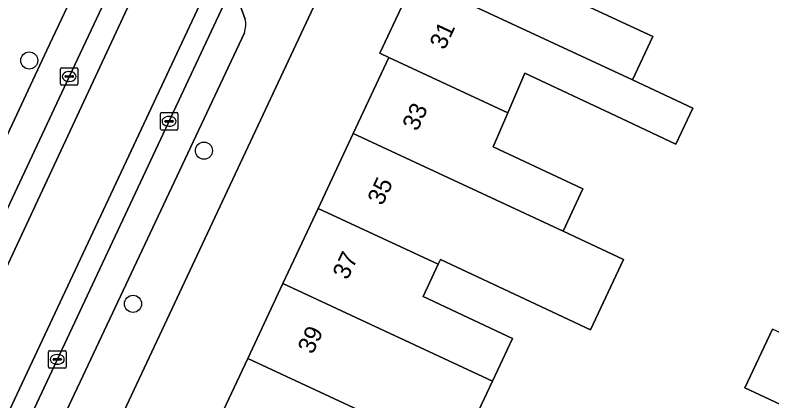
# Model space of a CAD drawing. Extents: x 159817 to 160765, y 380688 to 381638.
# Drawn here: x 160172.67 to 160215.98, y 381447.69 to 381469.78 of the extents above; entities that cross this region are included whole.
import ezdxf

# ---------------------------------------------------------------- set-up
doc = ezdxf.new("R2010")
doc.units = 0
for name, color, linetype in [('IMGEO_Boom', 7, 'Continuous'), ('IMGEO_Erf', 7, 'Continuous'), ('IMGEO_Kolk', 7, 'Continuous'), ('IMGEO_Pand', 7, 'Continuous'), ('IMGEO_Pand_nummerreeks', 7, 'Continuous'), ('IMGEO_Parkeervlak_open', 7, 'Continuous'), ('IMGEO_Rijbaan_lokaal_gesloten', 7, 'Continuous'), ('IMGEO_Voetpad_open', 7, 'Continuous')]:
    doc.layers.add(name, color=color, linetype=linetype)

msp = doc.modelspace()

# ---------------------------------------------------------------- linework, layer by layer
at = {"layer": 'IMGEO_Boom'}
for centre in [(160173.484, 381467.183), (160183.481, 381462.021), (160179.421, 381453.251)]:
    msp.add_circle(centre, 0.489, dxfattribs=at)
at = {"layer": 'IMGEO_Erf'}
for points in [[(160172.106, 381420.527), (160173.906, 381424.363), (160175.92, 381428.657), (160177.933, 381432.951), (160179.947, 381437.246), (160181.961, 381441.54), (160183.974, 381445.834), (160185.989, 381450.129), (160188.002, 381454.423), (160190.016, 381458.718), (160192.029, 381463.01), (160194.069, 381467.36), (160193.546, 381467.606), (160195.55, 381471.879), (160197.584, 381476.216), (160197.129, 381476.429), (160199.262, 381480.978), (160201.503, 381485.755), (160199.508, 381486.738), (160197.851, 381487.555), (160159.202, 381405.137)], [(160203.985, 381470.986), (160209.172, 381468.554), (160208.007, 381466.071), (160211.452, 381464.455), (160210.489, 381462.401), (160207.044, 381464.017), (160201.848, 381466.454), (160200.865, 381464.184), (160200.025, 381462.242), (160205.171, 381459.829), (160204.036, 381457.408), (160207.487, 381455.79), (160205.6, 381451.766), (160202.149, 381453.384), (160197.009, 381455.781), (160196.884, 381455.515), (160196.019, 381453.67), (160201.137, 381451.27), (160199.993, 381448.832), (160199.021, 381446.759)], [(160217.334, 381447.084), (160214.435, 381448.436), (160216.017, 381451.806)]]:
    msp.add_lwpolyline(points, dxfattribs=at)
at = {"layer": 'IMGEO_Kolk'}
for p, q in [((160175.267, 381465.842), (160175.267, 381466.694)), ((160175.342, 381466.768), (160176.194, 381466.768)), ((160176.268, 381466.694), (160176.268, 381465.842)), ((160175.526, 381466.262), (160175.526, 381466.274)), ((160175.964, 381466.225), (160175.566, 381466.225)), ((160175.569, 381466.311), (160175.967, 381466.311)), ((160175.755, 381466.548), (160175.78, 381466.548)), ((160176.01, 381466.274), (160176.01, 381466.262)), ((160176.194, 381465.768), (160175.342, 381465.768)), ((160175.778, 381465.988), (160175.753, 381465.988)), ((160180.985, 381463.278), (160180.985, 381464.13)), ((160181.06, 381464.204), (160181.912, 381464.204)), ((160181.986, 381464.13), (160181.986, 381463.278)), ((160181.244, 381463.698), (160181.244, 381463.71)), ((160181.682, 381463.661), (160181.284, 381463.661)), ((160181.287, 381463.747), (160181.685, 381463.747)), ((160181.473, 381463.984), (160181.498, 381463.984)), ((160181.728, 381463.71), (160181.728, 381463.698)), ((160181.912, 381463.204), (160181.06, 381463.204)), ((160181.496, 381463.424), (160181.471, 381463.424)), ((160174.588, 381449.643), (160174.588, 381450.495)), ((160174.663, 381450.569), (160175.515, 381450.569)), ((160175.076, 381450.349), (160175.101, 381450.349)), ((160175.589, 381450.495), (160175.589, 381449.643)), ((160174.847, 381450.063), (160174.847, 381450.075)), ((160175.285, 381450.026), (160174.887, 381450.026)), ((160174.89, 381450.112), (160175.288, 381450.112)), ((160175.099, 381449.789), (160175.074, 381449.789)), ((160175.331, 381450.075), (160175.331, 381450.063)), ((160175.515, 381449.569), (160174.663, 381449.569))]:
    msp.add_line(p, q, dxfattribs=at)
for points in [[(160175.267, 381465.842), (160175.267, 381466.694)], [(160175.342, 381466.768), (160176.194, 381466.768)], [(160176.268, 381466.694), (160176.268, 381465.842)], [(160176.194, 381465.768), (160175.342, 381465.768)], [(160180.985, 381463.278), (160180.985, 381464.13)], [(160181.06, 381464.204), (160181.912, 381464.204)], [(160181.986, 381464.13), (160181.986, 381463.278)], [(160181.912, 381463.204), (160181.06, 381463.204)], [(160174.588, 381449.643), (160174.588, 381450.495)], [(160174.663, 381450.569), (160175.515, 381450.569)], [(160175.589, 381450.495), (160175.589, 381449.643)], [(160175.515, 381449.569), (160174.663, 381449.569)]]:
    msp.add_lwpolyline(points, dxfattribs=at)
for centre, radius, start, end in [((160175.344, 381466.692), 0.0765, 91.552, 178.448), ((160175.344, 381466.692), 0.0765, 91.552, 178.448), ((160176.192, 381466.692), 0.0765, 1.552, 88.448), ((160176.192, 381466.692), 0.0765, 1.552, 88.448), ((160175.566, 381466.271), 0.0403, 85.8775, 175.7526), ((160175.563, 381466.261), 0.0366, 178.938, 274.7102), ((160175.967, 381466.268), 0.043, 264.8664, 352.4533), ((160175.971, 381466.273), 0.0386, 1.7309, 96.639), ((160175.344, 381465.844), 0.0765, 181.552, 268.448), ((160175.344, 381465.844), 0.0765, 181.552, 268.448), ((160176.192, 381465.844), 0.0765, 271.552, 358.448), ((160176.192, 381465.844), 0.0765, 271.552, 358.448), ((160181.062, 381464.128), 0.0765, 91.552, 178.448), ((160181.062, 381464.128), 0.0765, 91.552, 178.448), ((160181.91, 381464.128), 0.0765, 1.552, 88.448), ((160181.91, 381464.128), 0.0765, 1.552, 88.448), ((160181.284, 381463.707), 0.0403, 85.8775, 175.7526), ((160181.281, 381463.697), 0.0366, 178.938, 274.7102), ((160181.685, 381463.704), 0.043, 264.8664, 352.4533), ((160181.689, 381463.709), 0.0386, 1.7309, 96.639), ((160181.062, 381463.28), 0.0765, 181.552, 268.448), ((160181.062, 381463.28), 0.0765, 181.552, 268.448), ((160181.91, 381463.28), 0.0765, 271.552, 358.448), ((160181.91, 381463.28), 0.0765, 271.552, 358.448), ((160174.665, 381450.493), 0.0765, 91.552, 178.448), ((160174.665, 381450.493), 0.0765, 91.552, 178.448), ((160175.513, 381450.493), 0.0765, 1.552, 88.448), ((160175.513, 381450.493), 0.0765, 1.552, 88.448), ((160174.887, 381450.072), 0.0403, 85.8775, 175.7526), ((160174.884, 381450.062), 0.0366, 178.938, 274.7102), ((160175.288, 381450.069), 0.043, 264.8664, 352.4533), ((160175.292, 381450.074), 0.0386, 1.7309, 96.639), ((160174.665, 381449.645), 0.0765, 181.552, 268.448), ((160174.665, 381449.645), 0.0765, 181.552, 268.448), ((160175.513, 381449.645), 0.0765, 271.552, 358.448), ((160175.513, 381449.645), 0.0765, 271.552, 358.448)]:
    msp.add_arc(centre, radius, start, end, dxfattribs=at)
for centre, major_axis, ratio, start_param, end_param in [((160175.754, 381466.268), (-0.387, 0.002), 0.722429, 4.712389, 7.853982), ((160175.779, 381466.268), (-0.39, 0.002), 0.717154, 1.570796, 4.712389), ((160181.472, 381463.704), (-0.387, 0.002), 0.722429, 4.712389, 7.853982), ((160181.497, 381463.704), (-0.39, 0.002), 0.717154, 1.570796, 4.712389), ((160175.075, 381450.069), (-0.387, 0.002), 0.722429, 4.712389, 7.853982), ((160175.1, 381450.069), (-0.39, 0.002), 0.717154, 1.570796, 4.712389)]:
    msp.add_ellipse(centre, major_axis=major_axis, ratio=ratio, start_param=start_param, end_param=end_param, dxfattribs=at)
at = {"layer": 'IMGEO_Pand'}
for points in [[(160195.55, 381471.879), (160208.007, 381466.071), (160209.172, 381468.554), (160203.985, 381470.986), (160204.898, 381472.932), (160197.634, 381476.32), (160197.584, 381476.216)], [(160195.55, 381471.879), (160193.546, 381467.606), (160194.069, 381467.36), (160200.865, 381464.184), (160201.848, 381466.454), (160207.044, 381464.017), (160210.489, 381462.401), (160211.452, 381464.455), (160208.007, 381466.071)], [(160200.865, 381464.184), (160194.069, 381467.36), (160192.029, 381463.01), (160204.036, 381457.408), (160205.171, 381459.829), (160200.025, 381462.242)], [(160192.029, 381463.01), (160190.016, 381458.718), (160196.884, 381455.515), (160197.009, 381455.781), (160202.149, 381453.384), (160205.6, 381451.766), (160207.487, 381455.79), (160204.036, 381457.408)], [(160188.002, 381454.423), (160199.993, 381448.832), (160201.137, 381451.27), (160196.019, 381453.67), (160196.884, 381455.515), (160190.016, 381458.718)], [(160188.002, 381454.423), (160185.989, 381450.129), (160197.264, 381444.87), (160198.306, 381447.094), (160199.021, 381446.759), (160199.993, 381448.832)], [(160218.916, 381450.454), (160216.017, 381451.806), (160214.435, 381448.436), (160217.334, 381447.084)], [(160183.974, 381445.834), (160195.977, 381440.238), (160197.12, 381442.677), (160196.396, 381443.017), (160197.264, 381444.87), (160185.989, 381450.129)]]:
    msp.add_lwpolyline(points, close=True, dxfattribs=at)
at = {"layer": 'IMGEO_Parkeervlak_open'}
for points in [[(160167.066, 381447.717), (160169.392, 381452.674), (160175.477, 381465.647), (160186.405, 381488.877), (160193.743, 381504.831), (160197.176, 381511.876), (160198.669, 381515.096)], [(160192.945, 381484.698), (160192.525, 381485.762), (160192.07, 381486.28), (160191.707, 381485.544), (160172.744, 381445.075)], [(160179.823, 381479.094), (160174.497, 381467.781), (160166.645, 381451.002)], [(160185.838, 381469.56), (160185.415, 381470.712)], [(160173.734, 381445.837), (160174.933, 381446.261), (160175.203, 381446.466), (160175.471, 381446.793), (160185.796, 381468.773)]]:
    msp.add_lwpolyline(points, dxfattribs=at)
msp.add_arc((160184.462, 381469.239), 1.413, 340.7535, 13.1368, dxfattribs=at)
at = {"layer": 'IMGEO_Rijbaan_lokaal_gesloten'}
for points in [[(160183.049, 381478.7), (160187.589, 381488.337), (160186.405, 381488.877), (160175.477, 381465.647), (160169.392, 381452.674), (160167.066, 381447.717), (160166.977, 381447.507), (160168.22, 381446.905), (160169.494, 381449.607)], [(160171.48, 381445.326), (160172.919, 381448.379), (160183.534, 381471.022), (160190.948, 381486.805), (160187.589, 381488.337), (160183.049, 381478.7), (160169.494, 381449.607), (160168.22, 381446.905)], [(160191.707, 381485.544), (160192.07, 381486.28), (160190.948, 381486.805), (160183.534, 381471.022), (160172.919, 381448.379), (160171.48, 381445.326), (160172.606, 381444.781), (160172.744, 381445.075)]]:
    msp.add_lwpolyline(points, close=True, dxfattribs=at)
at = {"layer": 'IMGEO_Voetpad_open'}
for points in [[(160118.21, 381314.096), (160118.127, 381317.544), (160158.582, 381403.815), (160159.202, 381405.137), (160197.851, 381487.555)], [(160166.645, 381451.002), (160174.497, 381467.781), (160179.823, 381479.094)], [(160185.415, 381470.712), (160185.838, 381469.56)], [(160185.796, 381468.773), (160175.471, 381446.793), (160175.203, 381446.466), (160174.933, 381446.261), (160173.734, 381445.837)]]:
    msp.add_lwpolyline(points, dxfattribs=at)
msp.add_arc((160184.462, 381469.239), 1.413, 340.7535, 13.1368, dxfattribs=at)

# ---------------------------------------------------------------- texts
at = {"layer": 'IMGEO_Pand_nummerreeks'}
for s, rotation, p in [('31', 64.9831, (160197.251, 381467.745)), ('33', 64.8761, (160195.689, 381463.091)), ('35', 64.876, (160193.693, 381458.833)), ('37', 64.8761, (160191.696, 381454.576)), ('39', 64.8761, (160189.7, 381450.318))]:
    msp.add_text(s, height=1, rotation=rotation, dxfattribs=at).set_placement(p)

doc.saveas('drawing.dxf')
